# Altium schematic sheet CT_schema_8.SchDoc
size 274 x 160 mm
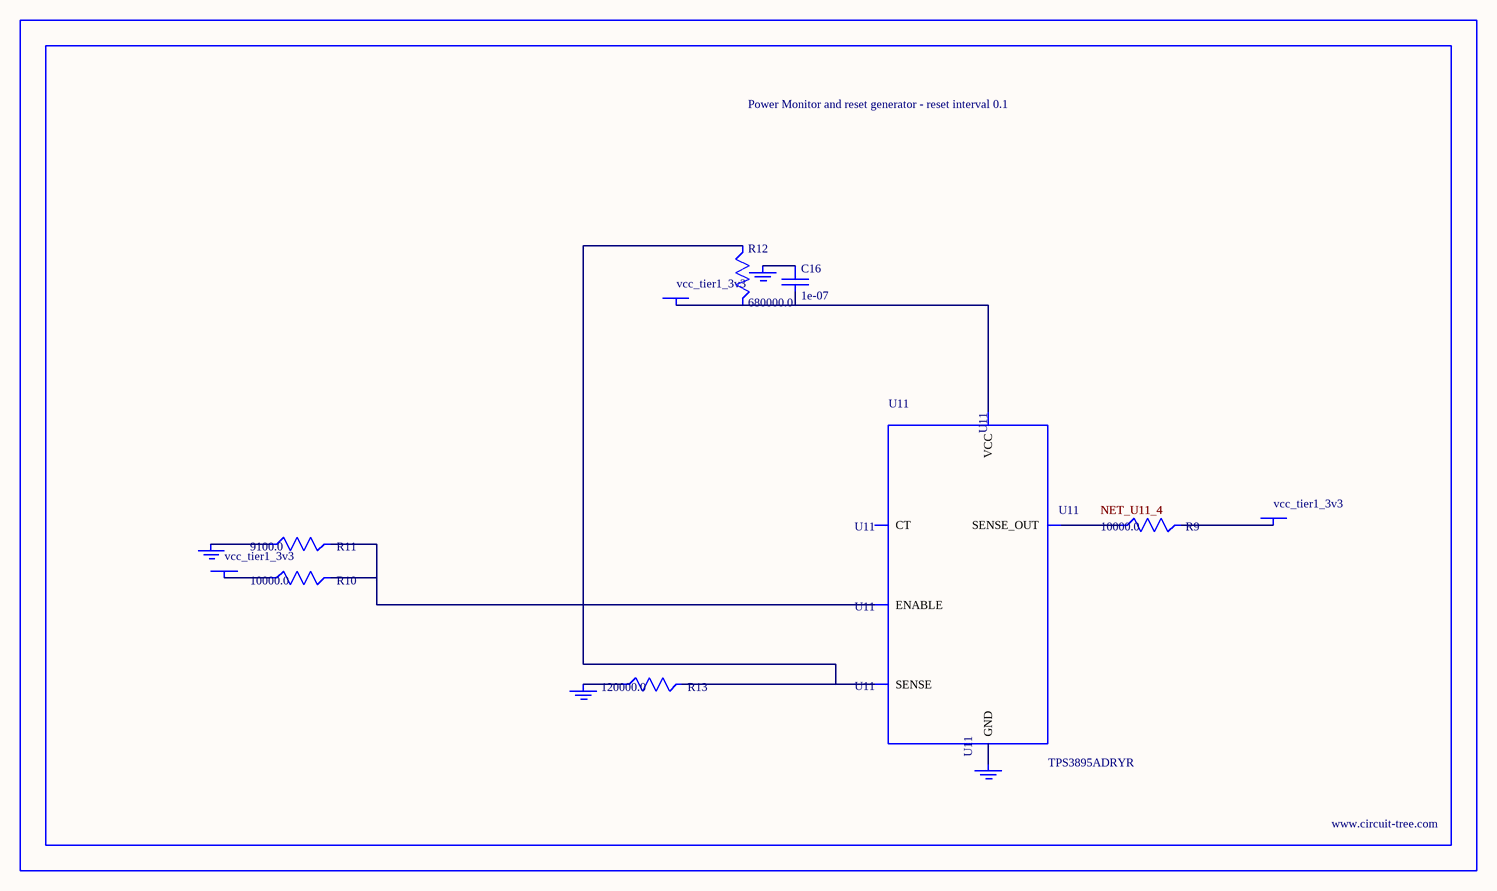
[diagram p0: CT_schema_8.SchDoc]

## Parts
BORDER7  (no value)
C16  1e-07  [C0402]
GND_INSTANCE_7_0  (no value)
GND_INSTANCE_7_1  (no value)
GND_INSTANCE_7_2  (no value)
GND_INSTANCE_7_3  (no value)
POWER_INSTANCE_7_0  vcc_tier1_3v3
POWER_INSTANCE_7_1  vcc_tier1_3v3
POWER_INSTANCE_7_2  vcc_tier1_3v3
R9  10000.0  [R0603]
R10  10000.0  [R0603]
R11  9100.0  [R0603]
R12  680000.0  [R0603]
R13  120000.0  [R0603]
U11  TPS3895ADRYR  [SON-6]

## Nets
NetC16_1: C16.1 GND_INSTANCE_7_2.0(GND)
NetC16_2: C16.2 POWER_INSTANCE_7_2.0(PWR) R12.2 U11.6(VCC)
NetGND_INSTANCE_7_0_0: GND_INSTANCE_7_0.0(GND) R11.1
NetGND_INSTANCE_7_1_0: GND_INSTANCE_7_1.0(GND) R13.1
NetGND_INSTANCE_7_3_0: GND_INSTANCE_7_3.0(GND) U11.2(GND)
NetPOWER_INSTANCE_7_0_0: POWER_INSTANCE_7_0.0(PWR) R10.1
NetPOWER_INSTANCE_7_1_0: POWER_INSTANCE_7_1.0(PWR) R9.2
NetR9_1: R9.1 U11.4(SENSE_OUT)
NetR10_2: R10.2 R11.2 U11.1(ENABLE)
NetR12_1: R12.1 R13.2 U11.3(SENSE)

Not connected (* = marked no-connect by the designer): U11 5(CT)

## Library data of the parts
BORDER7 = BORDER_PAGE7
C16 = C0402C104K3RACTU
GND_INSTANCE_7_0-GND_INSTANCE_7_3 = GND
POWER_INSTANCE_7_0-POWER_INSTANCE_7_2 = PWR
R9 R10 = RC0603JR-0710KL
R11 = RC0603JR-079K1L
R12 = RC0603JR-07680KL
R13 = RC0603JR-07120KL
